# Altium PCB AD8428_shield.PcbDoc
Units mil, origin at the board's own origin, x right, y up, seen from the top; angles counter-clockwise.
Board outline 688 x 400 mil, 2 copper layers (Top, Bottom), stack 61.811 mil thick; 3 components, 8 nets, 16 pads, 0 vias.
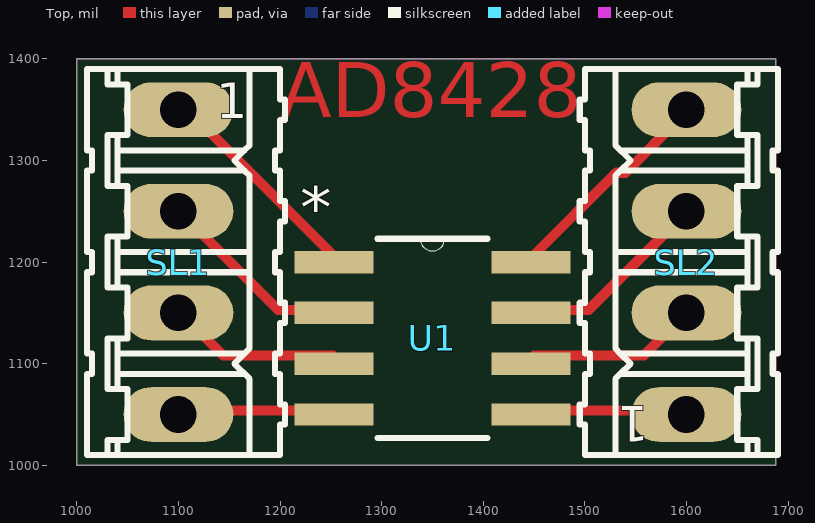
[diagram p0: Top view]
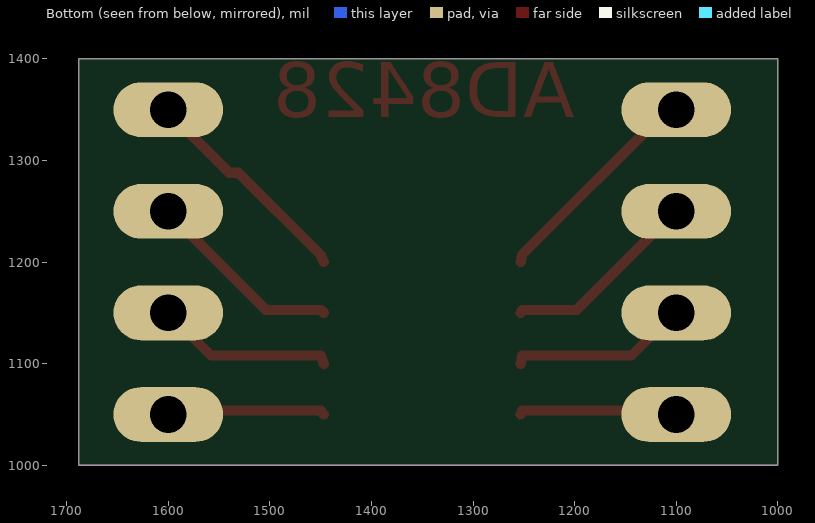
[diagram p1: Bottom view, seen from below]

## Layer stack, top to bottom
Top Solder: solder mask 0.4, Solder Resist, Dk 3.5
Top: signal copper 1.378
Dielectric 1: core 59.0551, FR-4, Dk 4.8
Bottom: signal copper 1.378
Bottom Solder: solder mask 0.4, Solder Resist, Dk 3.5

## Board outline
1000,1000 1688,1000 1688,1400 1000,1400

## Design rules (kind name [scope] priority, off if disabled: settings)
Clearance mdViaVia [IsVia vs IsVia] p1: gap=8
Clearance mdPadVia [IsPad vs IsVia] p2: gap=8
Clearance mdPadPad [IsPad vs IsPad] p3: gap=8
Clearance mdWireVia [(InLayerClass('Signal Layers') AND IsTrack) vs IsVia] p4: gap=8
Clearance mdWirePad [(InLayerClass('Signal Layers') AND IsTrack) vs IsPad] p5: gap=8
Clearance mdWireWire [(InLayerClass('Signal Layers') AND IsTrack) vs (InLayerClass('Signal Layers') AND IsTrack)] p6: gap=8
Clearance [All] p7: gap=8
HoleSize [All] p1: absolutevalues=TRUE maxlimit=100000 minlimit=24 maxpercent=80.000 minpercent=20.000
HoleToHoleClearance [All] p1: gap=8 allowstackedmicrovias=TRUE
PolygonConnect ThermalVias [IsVia] p1: connectstyle=Direct reliefconductorwidth=10 reliefentries=4 polygonreliefangle="90 Angle" airgapwidth=10
PolygonConnect [All] p2: connectstyle=Relief reliefconductorwidth=10 reliefentries=4 polygonreliefangle="90 Angle" airgapwidth=10
RoutingVias [All] p1: holewidth=28 width=50 viastyle="Through Hole" minholewidth=28 minwidth=50 maxholewidth=28 maxwidth=50
SilkToSilkClearance [All] p1 off: silktosilkclearance=10
SilkToSolderMaskClearance [IsPad] p1 off: minsilkscreentomaskgap=10 clearancetoexposedcopper=TRUE
SolderMaskExpansion [All] p1: expansion=4
UnpouredPolygon [All] p1: allowunpoured=FALSE
Width [All] p1: maxlimit=100000 minlimit=10 preferedwidth=10
25 further rules are at their usual default settings.

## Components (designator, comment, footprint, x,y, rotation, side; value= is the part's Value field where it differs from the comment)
SL1 "" 04P 1100,1200 r270 top
SL2 "" 04P 1600,1200 r90 top
U1 "AD8428ARZ" SOIC127P600X175-8N 1350,1125 r0 top

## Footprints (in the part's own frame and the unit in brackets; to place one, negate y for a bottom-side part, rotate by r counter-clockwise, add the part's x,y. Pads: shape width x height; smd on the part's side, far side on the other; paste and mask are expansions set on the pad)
04P [mil] "04P"
  oval 54x108 hole 36: 1(-150,0) 2(-50,0) 3(50,0) 4(150,0)
  silkscreen extent -190,-90 190,105
SOIC127P600X175-8N [mil] "SOIC127P600X175-8N"
  rect 78x22 smd: 1(-97,75) 2(-97,25) 3(-97,-25) 4(-97,-75) 5(97,-75) 6(97,-25) 7(97,25) 8(97,75)
  silkscreen extent -54,-98 54,98

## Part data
SL1 SL2: library part 04P
U1: library part SOIC127P600X175-8N

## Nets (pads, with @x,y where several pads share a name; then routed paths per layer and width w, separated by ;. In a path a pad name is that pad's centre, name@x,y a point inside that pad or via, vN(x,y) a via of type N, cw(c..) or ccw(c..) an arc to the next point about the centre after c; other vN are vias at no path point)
N$1: SL1.1 U1.1 | length 218.8
  Top w10: SL1.1 1108,1351 1252,1207 U1.1
N$2: SL1.2 U1.2 | length 195.1
  Top w10: SL1.2 1108,1243 1198,1153 1252,1153 U1.2
N$3: SL1.3 U1.3 | length 177
  Top w10: SL1.3 1108,1144 1144,1108 1252,1108 U1.3
N$4: SL1.4 U1.4 | length 157.1
  Top w10: SL1.4 1108,1054 1252,1054 U1.4
N$5: SL2.1 U1.5 | length 156.2
  Top w10: U1.5 1450,1054 1594,1054 SL2.1
N$6: SL2.2 U1.6 | length 175.9
  Top w10: U1.6 1450,1108 1558,1108 SL2.2
N$7: SL2.3 U1.7 | length 194.7
  Top w10: U1.7 1450,1153 1504,1153 1594,1243 SL2.3
N$8: SL2.4 U1.8 | length 217.5
  Top w10: U1.8 1450,1207 1531,1288 1540,1288 1594,1342 SL2.4

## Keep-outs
Keep-Out Layer:
  the board outline again, w0

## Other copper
Top:
  text "AD8428" at 1200,1325 h93

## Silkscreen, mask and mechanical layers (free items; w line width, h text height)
Dimension:
  the board outline again, w0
